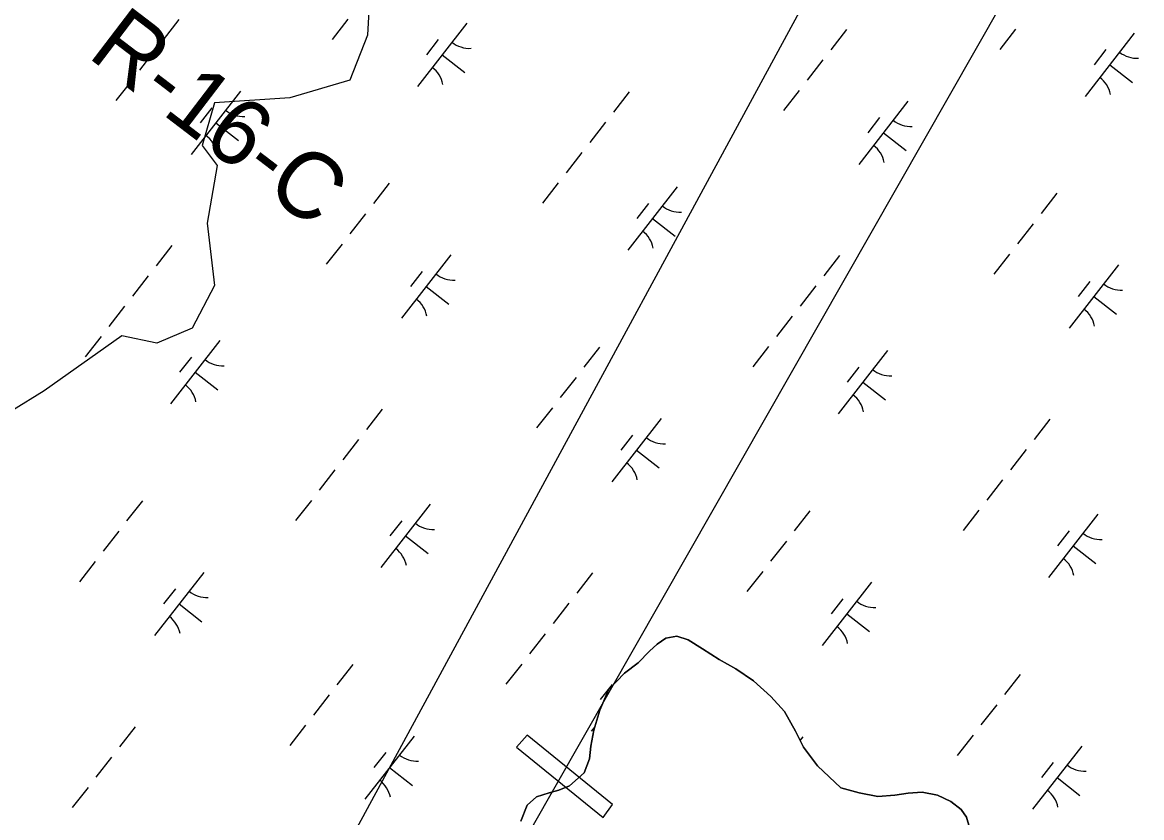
# Model space of a CAD drawing. Extents: x 3888273 to 3909528, y 158682 to 181032.
# Drawn here: x 3903461 to 3904160, y 171408 to 171905 of the extents above; entities that cross this region are included whole.
import ezdxf

# ---------------------------------------------------------------- set-up
doc = ezdxf.new("R2010")
doc.units = 0
for name, color, linetype in [('V-CHAN-DOCK', 7, 'Continuous'), ('V-RIVR-EDGE', 7, 'Continuous'), ('V-RIVR-RANG-IDEN', 7, 'Continuous'), ('V-TOPO-SHOR', 7, 'Continuous'), ('V-UTIL-LINE', 7, 'Continuous'), ('V-WETL-SWMP', 7, 'Continuous')]:
    doc.layers.add(name, color=color, linetype=linetype)

msp = doc.modelspace()

# ---------------------------------------------------------------- linework, layer by layer
at = {"layer": 'V-CHAN-DOCK'}
msp.add_lwpolyline([(3903769.57, 171452.47), (3903823.5, 171408.53), (3903829.49, 171416.52), (3903776.23, 171459.79)], close=True, dxfattribs=at)
at = {"layer": 'V-RIVR-EDGE'}
msp.add_lwpolyline([(3903677.98, 171923.27), (3903676.42, 171896.69), (3903665.47, 171868.56), (3903627.96, 171857.62), (3903581.07, 171854.49), (3903573.25, 171827.92), (3903582.63, 171815.41), (3903576.38, 171779.46), (3903581.07, 171740.38), (3903567, 171713.81), (3903545.12, 171704.43), (3903523.23, 171709.12), (3903474.78, 171674.73), (3903454.46, 171662.23), (3903409.13, 171646.6), (3903384.12, 171648.16), (3903329.41, 171701.31), (3903326.29, 171702.46)], dxfattribs=at)
at = {"layer": 'V-TOPO-SHOR'}
msp.add_lwpolyline([(3903772.25, 171406.15), (3903776.11, 171416.13), (3903782.02, 171421.35), (3903789.94, 171423.82), (3903795.88, 171425.47), (3903802.6, 171428.32), (3903811.65, 171436.36), (3903815.14, 171445.14), (3903815.85, 171453.09), (3903817.73, 171463.04), (3903821.57, 171475.39), (3903827, 171488.17), (3903836.82, 171498.6), (3903845.49, 171505.04), (3903852.57, 171512.27), (3903857.29, 171516.69), (3903862.81, 171520.32), (3903869.55, 171521.58), (3903876.72, 171519.27), (3903885.52, 171513.8), (3903895.92, 171507.16), (3903906.31, 171501.31), (3903917.51, 171493.88), (3903928.34, 171484.06), (3903936.78, 171474.62), (3903943.66, 171462.37), (3903948.53, 171452.49), (3903957.4, 171440.67), (3903971.84, 171426.92), (3903983.39, 171423.86), (3903994.94, 171421.6), (3904005.65, 171422.51), (3904013.98, 171423.79), (3904022.72, 171424.27), (3904032.27, 171422.39), (3904040.65, 171418.5), (3904047.06, 171413.41), (3904050.29, 171408.67), (3904052.34, 171402.34)], dxfattribs=at)
at = {"layer": 'V-UTIL-LINE'}
for points in [[(3905528.73, 173697.07), (3904376.91, 172459.2), (3904350.43, 172426.1), (3904072.41, 171916.39), (3903483.26, 170883.72), (3902993.41, 170023.17), (3902953.69, 169950.36), (3902854.4, 169652.47), (3902708.76, 169268.53)], [(3902927.21, 169208.96), (3902847.78, 169559.8), (3902827.92, 169778.25), (3902907.35, 170023.17), (3903370.73, 170850.63), (3904006.21, 172022.3), (3904694.65, 172743.84), (3905561.82, 173663.97)]]:
    msp.add_lwpolyline(points, dxfattribs=at)
at = {"layer": 'V-WETL-SWMP'}
for p, q in [((3903558.82, 171906.37), (3903549, 171893.75)), ((3903664.28, 171906.62), (3903654.46, 171893.99)), ((3903738.43, 171904.14), (3903707.72, 171864.68)), ((3903975.49, 171900.15), (3903965.66, 171887.52)), ((3904080.95, 171900.39), (3904071.13, 171887.76)), ((3903720.67, 171893.89), (3903713.3, 171884.41)), ((3904155.09, 171897.92), (3904124.39, 171858.46)), ((3903544.08, 171887.43), (3903534.26, 171874.8)), ((3904137.34, 171887.66), (3904129.97, 171878.19)), ((3903723.08, 171884.41), (3903737.28, 171873.36)), ((3903960.75, 171881.21), (3903950.93, 171868.58)), ((3904139.74, 171878.19), (3904153.95, 171867.13)), ((3903529.35, 171868.49), (3903519.52, 171855.86)), ((3903597.19, 171861.69), (3903566.48, 171822.23)), ((3903839.78, 171861.3), (3903829.95, 171848.67)), ((3903946.01, 171862.26), (3903936.19, 171849.64)), ((3903579.43, 171851.44), (3903572.06, 171841.97)), ((3904013.85, 171855.47), (3903983.15, 171816.01)), ((3903996.1, 171845.21), (3903988.73, 171835.74)), ((3903581.83, 171841.96), (3903596.04, 171830.91)), ((3903825.04, 171842.36), (3903815.22, 171829.73)), ((3903998.5, 171835.74), (3904012.71, 171824.68)), ((3903810.3, 171823.41), (3903800.48, 171810.79)), ((3903690.1, 171804.23), (3903680.28, 171791.6)), ((3903795.56, 171804.47), (3903785.74, 171791.84)), ((3903869.71, 171802), (3903839, 171762.54)), ((3904106.77, 171798), (3904096.94, 171785.38)), ((3903851.95, 171791.74), (3903844.58, 171782.27)), ((3903675.36, 171785.29), (3903665.54, 171772.66)), ((3903854.36, 171782.27), (3903868.56, 171771.21)), ((3904092.03, 171779.06), (3904082.21, 171766.43)), ((3903660.63, 171766.35), (3903650.8, 171753.72)), ((3903554.39, 171765.38), (3903544.57, 171752.75)), ((3903728.47, 171759.55), (3903697.76, 171720.09)), ((3903971.06, 171759.15), (3903961.23, 171746.52)), ((3904077.29, 171760.12), (3904067.47, 171747.49)), ((3904145.13, 171753.32), (3904114.43, 171713.86)), ((3903539.65, 171746.44), (3903529.83, 171733.81)), ((3903710.71, 171749.29), (3903703.34, 171739.82)), ((3903713.11, 171739.82), (3903727.32, 171728.77)), ((3903956.32, 171740.21), (3903946.5, 171727.58)), ((3904127.38, 171743.07), (3904120.01, 171733.6)), ((3904129.78, 171733.59), (3904143.99, 171722.54)), ((3903524.92, 171727.49), (3903515.09, 171714.87)), ((3903941.58, 171721.27), (3903931.76, 171708.64)), ((3903510.18, 171708.55), (3903500.35, 171695.93)), ((3903584.32, 171706.08), (3903553.62, 171666.62)), ((3903821.38, 171702.08), (3903811.56, 171689.46)), ((3903926.85, 171702.33), (3903917.02, 171689.7)), ((3904000.99, 171699.85), (3903970.28, 171660.39)), ((3903566.56, 171695.82), (3903559.2, 171686.35)), ((3903983.23, 171689.6), (3903975.86, 171680.13)), ((3903568.97, 171686.35), (3903583.18, 171675.3)), ((3903806.64, 171683.14), (3903796.82, 171670.51)), ((3903985.64, 171680.12), (3903999.84, 171669.07)), ((3903685.67, 171663.23), (3903675.85, 171650.61)), ((3903791.91, 171664.2), (3903782.08, 171651.57)), ((3903859.75, 171657.41), (3903829.04, 171617.94)), ((3904102.34, 171657.01), (3904092.51, 171644.38)), ((3903670.93, 171644.29), (3903661.11, 171631.66)), ((3903841.99, 171647.15), (3903834.62, 171637.68)), ((3903844.4, 171637.67), (3903858.6, 171626.62)), ((3904087.6, 171638.07), (3904077.78, 171625.44)), ((3903656.2, 171625.35), (3903646.37, 171612.72)), ((3904072.86, 171619.12), (3904063.04, 171606.5)), ((3903536, 171606.17), (3903526.17, 171593.54)), ((3903641.46, 171606.41), (3903631.63, 171593.78)), ((3903715.6, 171603.94), (3903684.9, 171564.47)), ((3903952.66, 171599.94), (3903942.84, 171587.31)), ((3904058.13, 171600.18), (3904048.3, 171587.55)), ((3903697.84, 171593.68), (3903690.48, 171584.21)), ((3904132.27, 171597.71), (3904101.57, 171558.25)), ((3903521.26, 171587.22), (3903511.43, 171574.6)), ((3904114.51, 171587.45), (3904107.14, 171577.98)), ((3903700.25, 171584.2), (3903714.46, 171573.15)), ((3903937.93, 171581), (3903928.1, 171568.37)), ((3904116.92, 171577.98), (3904131.12, 171566.92)), ((3903506.52, 171568.28), (3903496.69, 171555.65)), ((3903574.36, 171561.49), (3903543.66, 171522.02)), ((3903816.95, 171561.09), (3903807.13, 171548.46)), ((3903923.19, 171562.06), (3903913.36, 171549.43)), ((3903556.6, 171551.23), (3903549.23, 171541.76)), ((3903991.03, 171555.26), (3903960.32, 171515.8)), ((3903973.27, 171545), (3903965.9, 171535.53)), ((3903559.01, 171541.76), (3903573.21, 171530.7)), ((3903802.22, 171542.15), (3903792.39, 171529.52)), ((3903975.68, 171535.53), (3903989.88, 171524.48)), ((3903787.48, 171523.21), (3903777.65, 171510.58)), ((3903857.29, 171516.69), (3903852.57, 171512.27)), ((3903862.81, 171520.32), (3903857.29, 171516.69)), ((3903869.55, 171521.58), (3903862.81, 171520.32)), ((3903876.73, 171519.27), (3903869.55, 171521.58)), ((3903885.52, 171513.8), (3903876.73, 171519.27)), ((3903852.57, 171512.27), (3903845.49, 171505.04)), ((3903895.92, 171507.16), (3903885.52, 171513.8)), ((3903667.28, 171504.02), (3903657.45, 171491.39)), ((3903772.74, 171504.26), (3903762.91, 171491.64)), ((3903845.49, 171505.04), (3903836.82, 171498.6)), ((3903906.31, 171501.31), (3903895.92, 171507.16)), ((3903917.51, 171493.88), (3903906.31, 171501.31)), ((3903836.82, 171498.6), (3903827, 171488.16)), ((3903928.34, 171484.06), (3903917.51, 171493.88)), ((3904083.94, 171497.8), (3904074.12, 171485.17)), ((3903827, 171488.16), (3903821.57, 171475.39)), ((3903829.13, 171491.53), (3903821.76, 171482.06)), ((3903652.54, 171485.08), (3903642.71, 171472.45)), ((3903936.78, 171474.62), (3903928.34, 171484.06)), ((3903821.57, 171475.39), (3903817.73, 171463.04)), ((3903943.66, 171462.38), (3903936.78, 171474.62)), ((3904069.21, 171478.85), (3904059.38, 171466.23)), ((3903637.8, 171466.14), (3903627.98, 171453.51)), ((3903531.57, 171465.17), (3903521.74, 171452.54)), ((3903705.64, 171459.34), (3903674.94, 171419.88)), ((3903817.73, 171463.04), (3903815.85, 171453.09)), ((3903818.39, 171465.17), (3903816.18, 171462.33)), ((3903948.53, 171452.49), (3903943.66, 171462.38)), ((3903948.23, 171458.94), (3903946.47, 171456.68)), ((3904054.47, 171459.91), (3904044.64, 171447.28)), ((3903815.85, 171453.09), (3903815.14, 171445.14)), ((3903957.4, 171440.67), (3903948.53, 171452.49)), ((3904122.31, 171453.12), (3904091.6, 171413.65)), ((3903516.83, 171446.23), (3903507, 171433.6)), ((3903687.88, 171449.08), (3903680.52, 171439.61)), ((3903815.14, 171445.14), (3903811.65, 171436.36)), ((3903690.29, 171439.61), (3903704.5, 171428.56)), ((3903971.84, 171426.92), (3903957.4, 171440.67)), ((3904104.55, 171442.86), (3904097.18, 171433.39)), ((3903811.65, 171436.36), (3903802.6, 171428.32)), ((3904106.96, 171433.38), (3904121.16, 171422.33)), ((3903502.09, 171427.29), (3903492.27, 171414.66)), ((3903789.94, 171423.82), (3903782.02, 171421.35)), ((3903795.88, 171425.47), (3903789.94, 171423.82)), ((3903802.6, 171428.32), (3903795.88, 171425.47)), ((3903983.39, 171423.86), (3903971.84, 171426.92)), ((3903994.94, 171421.6), (3903983.39, 171423.86)), ((3904022.72, 171424.27), (3904013.98, 171423.79)), ((3904032.27, 171422.39), (3904022.72, 171424.27)), ((3903782.02, 171421.35), (3903776.11, 171416.13)), ((3904005.65, 171422.51), (3903994.94, 171421.6)), ((3904013.98, 171423.79), (3904005.65, 171422.51)), ((3904040.65, 171418.5), (3904032.27, 171422.39)), ((3904047.06, 171413.41), (3904040.65, 171418.5)), ((3903776.11, 171416.13), (3903772.25, 171406.15)), ((3904050.29, 171408.67), (3904047.06, 171413.41)), ((3904052.34, 171402.34), (3904050.29, 171408.67))]:
    msp.add_line(p, q, dxfattribs=at)
for centre, start, end in [((3903740.22, 171906.07), 231.34298, 272.88664), ((3904156.89, 171899.84), 231.34298, 272.88664), ((3903706.3, 171862.47), 11.34298, 52.88663), ((3904122.97, 171856.24), 11.34298, 52.88663), ((3903598.98, 171863.62), 231.34298, 272.88664), ((3904015.65, 171857.39), 231.34298, 272.88664), ((3903565.06, 171820.02), 11.34298, 52.88663), ((3903981.73, 171813.79), 11.34298, 52.88663), ((3903871.51, 171803.92), 231.34298, 272.88664), ((3903837.58, 171760.32), 11.34298, 52.88663), ((3903730.26, 171761.47), 231.34298, 272.88664), ((3904146.93, 171755.25), 231.34298, 272.88664), ((3903696.34, 171717.87), 11.34298, 52.88663), ((3904113.01, 171711.65), 11.34298, 52.88663), ((3903586.12, 171708), 231.34298, 272.88664), ((3904002.79, 171701.78), 231.34298, 272.88664), ((3903552.19, 171664.4), 11.34298, 52.88663), ((3903968.86, 171658.18), 11.34298, 52.88663), ((3903861.54, 171659.33), 231.34298, 272.88664), ((3903827.62, 171615.73), 11.34298, 52.88663), ((3903717.4, 171605.86), 231.34298, 272.88664), ((3904134.07, 171599.63), 231.34298, 272.88664), ((3903683.48, 171562.26), 11.34298, 52.88663), ((3904100.14, 171556.03), 11.34298, 52.88663), ((3903576.16, 171563.41), 231.34298, 272.88664), ((3903992.83, 171557.18), 231.34298, 272.88664), ((3903542.23, 171519.81), 11.34298, 52.88663), ((3903958.9, 171513.58), 11.34298, 52.88663), ((3903707.44, 171461.26), 231.34298, 272.88664), ((3904124.11, 171455.04), 231.34298, 272.88664), ((3903673.51, 171417.66), 11.34298, 52.88663), ((3904090.18, 171411.44), 11.34298, 52.88663)]:
    msp.add_arc(centre, 17.62, start, end, dxfattribs=at)

# ---------------------------------------------------------------- texts
at = {"layer": 'V-RIVR-RANG-IDEN'}
msp.add_text('R-16-C', height=41.5, rotation=322.65659, dxfattribs=at).set_placement((3903500.93, 171883.53))

doc.saveas('drawing.dxf')
